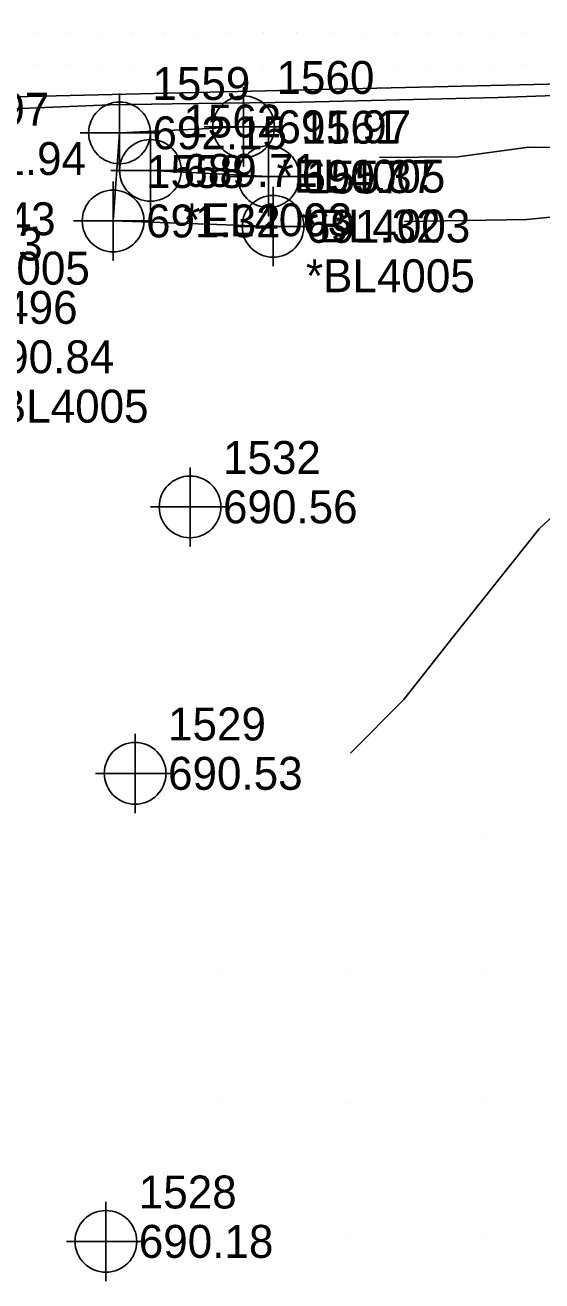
# Model space of a CAD drawing. Extents: x 1755643 to 1760494, y 736519 to 737621.
# Drawn here: x 1758050.6 to 1758089.9, y 736891.4 to 736986.8 of the extents above; entities that cross this region are included whole.
import ezdxf

# ---------------------------------------------------------------- set-up
doc = ezdxf.new("R2010")
doc.units = 0
for name, color, linetype in [('Exist Horizontal Alignment Curve and Spiral Data', 7, 'Continuous'), ('Exist Horizontal Alignment Direction Label', 7, 'Continuous'), ('Exist Railroads Standard Gauge', 7, 'Continuous'), ('Exist Roads EOT', 7, 'Continuous'), ('Old_Level_1', 7, 'Continuous'), ('Old_Level_10', 7, 'Continuous'), ('Old_Level_2', 7, 'Continuous'), ('Old_Level_3', 7, 'Continuous'), ('Prop Corridor Linear Feature', 7, 'Continuous'), ('Prop Dimension', 7, 'Continuous'), ('Prop EOT Dash', 7, 'Continuous'), ('Prop Horizontal Alignment Direction Label', 7, 'Continuous'), ('Prop Lane Lines', 7, 'Continuous'), ('Prop Paint Stripe', 7, 'Continuous'), ('Prop Paved Shoulder', 7, 'Continuous'), ('Scratch_Level_1', 7, 'Continuous'), ('Scratch_Level_2', 7, 'Continuous'), ('Scratch_Level_5', 7, 'Continuous'), ('Scratch_Level_9', 7, 'Continuous')]:
    doc.layers.add(name, color=color, linetype=linetype)

msp = doc.modelspace()

# ---------------------------------------------------------------- linework, layer by layer
at = {"layer": 'Exist Horizontal Alignment Curve and Spiral Data'}
for points in [[(1758063.181, 736953.217), (1758063.181, 736947.217), (1758063.181, 736950.217), (1758066.181, 736950.217), (1758060.181, 736950.217)], [(1758059.007, 736932.98), (1758059.007, 736926.98), (1758059.007, 736929.98), (1758062.007, 736929.98), (1758056.007, 736929.98)], [(1758056.784, 736897.437), (1758056.784, 736891.437), (1758056.784, 736894.437), (1758059.784, 736894.437), (1758053.784, 736894.437)]]:
    msp.add_lwpolyline(points, dxfattribs=at)
for centre in [(1758063.181, 736950.217), (1758059.007, 736929.98), (1758056.784, 736894.437)]:
    msp.add_circle(centre, 2.344, dxfattribs=at)
at = {"layer": 'Exist Railroads Standard Gauge'}
for points in [[(1758108.462, 736981.277), (1758109.427, 736980.335), (1758110.14, 736979.299), (1758110.783, 736977.168), (1758110.952, 736974.303), (1758110.352, 736969.705), (1758107.278, 736963.204), (1758101.809, 736958.968), (1758095.31, 736953.74), (1758089.696, 736948.55), (1758083.158, 736940.339), (1758079.418, 736935.58), (1758075.362, 736931.502)], [(1758077.571, 736976.738), (1758083.517, 736976.79), (1758088.891, 736977.537), (1758100.927, 736977.453), (1758107.416, 736977.504)], [(1758079.46, 736971.886), (1758088.761, 736972.044), (1758094.567, 736972.615), (1758102.321, 736971.414), (1758107.188, 736972.41), (1758108.976, 736975.095)]]:
    msp.add_lwpolyline(points, dxfattribs=at)
at = {"layer": 'Old_Level_10'}
for points in [[(1758060.168, 736978.768), (1758060.168, 736972.768), (1758060.168, 736975.768), (1758063.168, 736975.768), (1758057.168, 736975.768)], [(1758069.143, 736978.297), (1758069.143, 736972.297), (1758069.143, 736975.297), (1758072.143, 736975.297), (1758066.143, 736975.297)]]:
    msp.add_lwpolyline(points, dxfattribs=at)
for centre in [(1758060.168, 736975.768), (1758069.143, 736975.297)]:
    msp.add_circle(centre, 2.344, dxfattribs=at)
at = {"layer": 'Prop Corridor Linear Feature'}
msp.add_lwpolyline([(1758061.811, 736980.821), (1758057.085, 736980.756), (1758049.092, 736980.415), (1758041.095, 736980.272), (1758035.133, 736980.136)], dxfattribs=at)
at = {"layer": 'Prop Dimension'}
msp.add_line((1758069.143, 736975.297), (1758060.168, 736975.768), dxfattribs=at)
at = {"layer": 'Prop Lane Lines'}
for points in [[(1758057.82, 736981.618), (1758057.82, 736975.618), (1758057.82, 736978.618), (1758060.82, 736978.618), (1758054.82, 736978.618)], [(1758067.246, 736982.078), (1758067.246, 736976.078), (1758067.246, 736979.078), (1758070.246, 736979.078), (1758064.246, 736979.078)], [(1758057.335, 736974.929), (1758057.335, 736968.929), (1758057.335, 736971.929), (1758060.335, 736971.929), (1758054.335, 736971.929)], [(1758069.486, 736974.519), (1758069.486, 736968.519), (1758069.486, 736971.519), (1758072.486, 736971.519), (1758066.486, 736971.519)]]:
    msp.add_lwpolyline(points, dxfattribs=at)
for centre in [(1758067.246, 736979.078), (1758057.82, 736978.618), (1758057.335, 736971.929), (1758069.486, 736971.519)]:
    msp.add_circle(centre, 2.344, dxfattribs=at)
at = {"layer": 'Prop Paint Stripe'}
for p, q in [((1758085.403, 736924.975), (1758085.403, 736924.975)), ((1758065.401, 736914.974), (1758065.401, 736914.974)), ((1758075.402, 736914.974), (1758075.402, 736914.974)), ((1758085.403, 736914.974), (1758085.403, 736914.974)), ((1758065.401, 736904.973), (1758065.401, 736904.973)), ((1758075.402, 736904.973), (1758075.402, 736904.973)), ((1758085.403, 736904.973), (1758085.403, 736904.973)), ((1758065.401, 736894.971), (1758065.401, 736894.971)), ((1758075.402, 736894.971), (1758075.402, 736894.971)), ((1758085.403, 736894.971), (1758085.403, 736894.971))]:
    msp.add_line(p, q, dxfattribs=at)
at = {"layer": 'Scratch_Level_1'}
for points in [[(1758107.37, 736981.986), (1758101.583, 736981.833), (1758086.597, 736981.296), (1758071.606, 736980.949), (1758065.778, 736980.876)], [(1758065.778, 736980.876), (1758061.811, 736980.821)]]:
    msp.add_lwpolyline(points, dxfattribs=at)
at = {"layer": 'Scratch_Level_2'}
for p, q in [((1758051.25, 736986.25), (1758051.25, 736986.25)), ((1758053.75, 736986.25), (1758053.75, 736986.25)), ((1758056.25, 736986.25), (1758056.25, 736986.25)), ((1758058.75, 736986.25), (1758058.75, 736986.25)), ((1758061.25, 736986.25), (1758061.25, 736986.25)), ((1758063.75, 736986.25), (1758063.75, 736986.25)), ((1758066.25, 736986.25), (1758066.25, 736986.25)), ((1758068.75, 736986.25), (1758068.75, 736986.25)), ((1758071.25, 736986.25), (1758071.25, 736986.25)), ((1758073.75, 736986.25), (1758073.75, 736986.25)), ((1758076.25, 736986.25), (1758076.25, 736986.25)), ((1758078.75, 736986.25), (1758078.75, 736986.25)), ((1758081.25, 736986.25), (1758081.25, 736986.25)), ((1758083.75, 736986.25), (1758083.75, 736986.25)), ((1758086.25, 736986.25), (1758086.25, 736986.25)), ((1758088.75, 736986.25), (1758088.75, 736986.25)), ((1758051.25, 736983.75), (1758051.25, 736983.75)), ((1758053.75, 736983.75), (1758053.75, 736983.75)), ((1758056.25, 736983.75), (1758056.25, 736983.75)), ((1758058.75, 736983.75), (1758058.75, 736983.75)), ((1758061.25, 736983.75), (1758061.25, 736983.75)), ((1758063.75, 736983.75), (1758063.75, 736983.75)), ((1758066.25, 736983.75), (1758066.25, 736983.75)), ((1758068.75, 736983.75), (1758068.75, 736983.75)), ((1758071.25, 736983.75), (1758071.25, 736983.75)), ((1758073.75, 736983.75), (1758073.75, 736983.75)), ((1758076.25, 736983.75), (1758076.25, 736983.75)), ((1758078.75, 736983.75), (1758078.75, 736983.75)), ((1758081.25, 736983.75), (1758081.25, 736983.75)), ((1758083.75, 736983.75), (1758083.75, 736983.75)), ((1758086.25, 736983.75), (1758086.25, 736983.75)), ((1758088.75, 736983.75), (1758088.75, 736983.75))]:
    msp.add_line(p, q, dxfattribs=at)
at = {"layer": 'Scratch_Level_5'}
for points in [[(1758265.123, 736986.802), (1758240.343, 736986.156), (1758230.069, 736985.969), (1758216.154, 736985.715), (1758208.539, 736985.417), (1758198.9, 736985.161), (1758191.555, 736985.031), (1758179.852, 736984.674), (1758172.722, 736984.478), (1758160.277, 736984.175), (1758146.914, 736983.818), (1758130.042, 736983.297), (1758116.65, 736982.973), (1758104.474, 736982.655), (1758077.369, 736982.002), (1758065.758, 736981.725)], [(1758065.758, 736981.725), (1758038.129, 736981.07), (1758029.226, 736980.816), (1758020.635, 736980.632), (1757997.713, 736980.082), (1757970.759, 736979.407), (1757939.721, 736978.58), (1757928.953, 736978.26), (1757915.672, 736977.877), (1757898.955, 736977.479), (1757878.164, 736976.8), (1757865.099, 736976.448)]]:
    msp.add_lwpolyline(points, dxfattribs=at)
at = {"layer": 'Scratch_Level_9'}
msp.add_lwpolyline([(1758069.486, 736971.519), (1758057.335, 736971.929), (1758057.82, 736978.618), (1758067.246, 736979.078)], dxfattribs=at)

# ---------------------------------------------------------------- texts
at = {"layer": 'Exist Horizontal Alignment Direction Label'}
for s, p in [('*EL4005', (1758069.746, 736974.078)), ('*EL4005', (1758042.739, 736967.095)), ('*BL4005', (1758071.986, 736966.519)), ('*BL4005', (1758047.199, 736956.616))]:
    msp.add_text(s, height=2.5, dxfattribs=at).set_placement(p)
at = {"layer": 'Exist Roads EOT'}
for s, p in [('1532', (1758065.681, 736952.717)), ('1529', (1758061.507, 736932.48)), ('1528', (1758059.284, 736896.937))]:
    msp.add_text(s, height=2.5, dxfattribs=at).set_placement(p)
at = {"layer": 'Old_Level_1'}
for s, p in [('1562', (1758062.668, 736978.268)), ('1561', (1758071.643, 736977.797))]:
    msp.add_text(s, height=2.5, dxfattribs=at).set_placement(p)
at = {"layer": 'Old_Level_2'}
for s, p in [('689.71', (1758062.668, 736974.518)), ('690.37', (1758071.643, 736974.047))]:
    msp.add_text(s, height=2.5, dxfattribs=at).set_placement(p)
at = {"layer": 'Old_Level_3'}
for s, p in [('692.15', (1758060.32, 736977.368)), ('691.97', (1758069.746, 736977.828)), ('691.94', (1758045.052, 736975.419)), ('690.43', (1758042.739, 736970.845)), ('691.32', (1758059.835, 736970.679)), ('691.32', (1758071.986, 736970.269)), ('690.84', (1758047.199, 736960.366))]:
    msp.add_text(s, height=2.5, dxfattribs=at).set_placement(p)
at = {"layer": 'Prop EOT Dash'}
for s, p in [('1559', (1758060.32, 736981.118)), ('1560', (1758069.746, 736981.578)), ('1497', (1758045.052, 736979.169)), ('1558', (1758059.835, 736974.429)), ('1557', (1758071.986, 736974.019)), ('1496', (1758047.199, 736964.116))]:
    msp.add_text(s, height=2.5, dxfattribs=at).set_placement(p)
at = {"layer": 'Prop Horizontal Alignment Direction Label'}
for s, p in [('*EL4003', (1758062.668, 736970.768)), ('*BL4003', (1758071.643, 736970.297)), ('*BL4003', (1758039.155, 736968.924))]:
    msp.add_text(s, height=2.5, dxfattribs=at).set_placement(p)
at = {"layer": 'Prop Paved Shoulder'}
for s, p in [('690.56', (1758065.681, 736948.967)), ('690.53', (1758061.507, 736928.73)), ('690.18', (1758059.284, 736893.187))]:
    msp.add_text(s, height=2.5, dxfattribs=at).set_placement(p)

doc.saveas('drawing.dxf')
